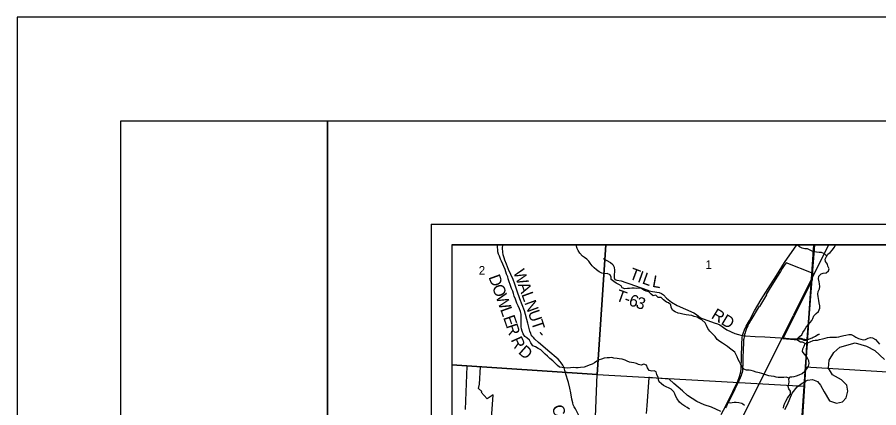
# Model space of a CAD drawing. Extents: x 39.8 to 73.8, y 13 to 35.
# Drawn here: x 39.763 to 43.927, y 33.079 to 34.965 of the extents above; entities that cross this region are included whole.
import ezdxf

# ---------------------------------------------------------------- set-up
doc = ezdxf.new("R2010")
doc.units = 0
for name, color, linetype in [('GM_X_Corporation', 7, 'Continuous'), ('GM_X_County_Road', 7, 'Continuous'), ('GM_X_County_Road_Text', 7, 'Continuous'), ('GM_X_Minor_River', 7, 'Continuous'), ('GM_X_Rail_Line', 7, 'Continuous'), ('GM_X_Section_Text', 7, 'Continuous'), ('GM_X_State_Route', 7, 'Continuous'), ('GM_X_Township_Road', 7, 'Continuous'), ('GM_X_Township_Road_Text', 7, 'Continuous'), ('SH_Border', 7, 'Continuous'), ('SH_Cut_Line', 7, 'Continuous'), ('SH_Data', 7, 'Continuous')]:
    doc.layers.add(name, color=color, linetype=linetype)

msp = doc.modelspace()

# ---------------------------------------------------------------- linework, layer by layer
at = {"layer": 'GM_X_Corporation'}
for points in [[(42.6077, 33.865), (41.863, 33.865), (41.863, 33.2861), (42.566, 33.2401)], [(43.6132, 33.865), (42.6077, 33.865), (42.566, 33.2401), (43.567, 33.1836), (43.573, 33.2772)], [(44.6253, 33.865), (43.6132, 33.865), (43.573, 33.2772), (44.5795, 33.2157)], [(41.863, 33.2861), (41.863, 32.2795), (42.505, 32.2334), (42.5452, 32.7074), (42.566, 33.2401)], [(43.573, 33.2772), (44.5795, 33.2157), (44.516, 32.1957), (43.5036, 32.2603), (43.567, 33.1836)], [(43.567, 33.1836), (43.5036, 32.2603), (43.4969, 32.1712), (42.505, 32.2334), (42.5452, 32.7074), (42.566, 33.2401)]]:
    msp.add_lwpolyline(points, close=True, dxfattribs=at)
for points in [[(43.3481, 29.9766), (43.3525, 30.036), (43.3561, 30.0855), (43.3611, 30.1536), (43.3611, 30.1764), (43.4119, 30.9413), (43.4278, 31.1804), (43.4594, 31.6102), (43.4604, 31.6234), (43.4879, 31.9992), (43.5004, 32.1696), (43.5417, 32.788), (43.542, 32.7932), (43.5449, 32.8368), (43.546, 32.8532), (43.5465, 32.861), (43.5681, 33.1854), (43.5817, 33.4098), (43.6158, 33.865), (41.863, 33.865), (41.863, 28.2309)], [(48.663, 33.865), (43.6158, 33.865), (43.5817, 33.4098), (43.5681, 33.1854), (43.5465, 32.861), (43.546, 32.8532), (43.5449, 32.8368), (43.542, 32.7932), (43.5417, 32.788), (43.5004, 32.1696), (43.4879, 31.9992), (43.4604, 31.6234), (43.4594, 31.6102), (43.4278, 31.1804), (43.4119, 30.9413), (43.3611, 30.1764), (43.3611, 30.1536), (43.3561, 30.0855), (43.3525, 30.036), (43.3481, 29.9766)], [(43.557, 33.0409), (43.5667, 33.1746), (43.5752, 33.2909), (43.5789, 33.3426), (43.5793, 33.3485), (43.5822, 33.3889), (43.5833, 33.4047), (43.5793, 33.4041), (43.5752, 33.4039), (43.5712, 33.404), (43.5671, 33.4044), (43.5632, 33.4053), (43.5593, 33.4064), (43.5498, 33.4096), (43.5472, 33.4103), (43.5445, 33.4106), (43.5418, 33.4104), (43.5391, 33.4099), (43.5337, 33.4084), (43.5298, 33.4075), (43.5259, 33.4069), (43.5218, 33.4067), (43.5178, 33.4069), (43.4639, 33.4121), (43.4658, 33.4158), (43.467, 33.4183), (43.6068, 33.6965), (43.6088, 33.7216), (43.6092, 33.7266), (43.4789, 33.7796), (43.4697, 33.7657), (43.4608, 33.7517), (43.452, 33.7375), (43.438, 33.7143), (43.4372, 33.7148), (43.4026, 33.6574), (43.3833, 33.6256), (43.3842, 33.6251), (43.3499, 33.5684), (43.3491, 33.5689), (43.309, 33.5025), (43.303, 33.4927), (43.298, 33.4839), (43.2934, 33.475), (43.2893, 33.4658), (43.2856, 33.4564), (43.2823, 33.4468), (43.2806, 33.4412), (43.2785, 33.433), (43.2778, 33.43), (43.2771, 33.4271), (43.2761, 33.4217), (43.2746, 33.4126), (43.2739, 33.4067), (43.2733, 33.4008), (43.273, 33.3962), (43.2727, 33.3903), (43.2727, 33.3899), (43.2727, 33.3894), (43.2726, 33.3885), (43.2718, 33.3614), (43.2704, 33.3175), (43.2697, 33.2938), (43.2696, 33.291), (43.2692, 33.2832), (43.2686, 33.2755), (43.2677, 33.2678), (43.2695, 33.2675), (43.2695, 33.2671), (43.2687, 33.2618), (43.2678, 33.2565), (43.2662, 33.2488), (43.2643, 33.2412), (43.2627, 33.2352), (43.2609, 33.2293), (43.2602, 33.2295), (43.2591, 33.2299), (43.2587, 33.2287), (43.2583, 33.2274), (43.2569, 33.2234), (43.254, 33.2158), (43.2509, 33.2083), (43.2475, 33.2009), (43.247, 33.1999), (43.2449, 33.1957), (43.2198, 33.1444), (43.2006, 33.1069), (43.1988, 33.1033), (43.1974, 33.1005), (43.1949, 33.0954), (43.1927, 33.0906), (43.1904, 33.0859), (43.1882, 33.0812), (43.186, 33.0765)], [(42.0545, 33.0285), (42.0613, 33.1171), (42.0632, 33.1409), (42.0336, 33.1218), (42.0049, 33.154), (42.0081, 33.1569), (41.9916, 33.1714), (41.9976, 33.1929), (42.0024, 33.2761), (41.9362, 33.2801), (41.9283, 33.0712)], [(43.1639, 33.0603), (43.119, 33.082), (43.0827, 33.0938), (43.0476, 33.1092), (43.0027, 33.1387), (42.9783, 33.16), (42.9364, 33.1965), (42.9144, 33.2176), (42.8338, 33.2233), (42.8184, 33.2243), (42.8154, 33.2245), (42.812, 33.178), (42.8053, 33.0892), (42.8024, 33.0506)]]:
    msp.add_lwpolyline(points, dxfattribs=at)
at = {"layer": 'GM_X_County_Road'}
for points in [[(42.4147, 33.2426), (42.4097, 33.2589), (42.4058, 33.2716), (42.3998, 33.2839), (42.3916, 33.296), (42.3865, 33.303), (42.3781, 33.3131), (42.3685, 33.3223), (42.3379, 33.3481), (42.2831, 33.3937), (42.2653, 33.4101), (42.2575, 33.4179), (42.2518, 33.4248), (42.2477, 33.4318), (42.2446, 33.4382), (42.2411, 33.4486), (42.2306, 33.4878), (42.2142, 33.5466), (42.1923, 33.6047), (42.18, 33.6428), (42.1685, 33.6765), (42.1599, 33.698), (42.1379, 33.747), (42.1275, 33.7724), (42.1201, 33.7919), (42.1162, 33.803), (42.1123, 33.8174), (42.1101, 33.8305), (42.109, 33.8502), (42.1097, 33.865)], [(42.5359, 32.9279), (42.5342, 32.9315), (42.5108, 32.9743), (42.4605, 33.0731), (42.4552, 33.0827), (42.4505, 33.0936), (42.4476, 33.1026), (42.4441, 33.1205), (42.4386, 33.1514), (42.4341, 33.1736), (42.4275, 33.2003), (42.4257, 33.206), (42.415, 33.2417), (42.4147, 33.2426)]]:
    msp.add_lwpolyline(points, dxfattribs=at)
at = {"layer": 'GM_X_Minor_River'}
for p, q in [((43.5792, 33.3903), (43.5951, 33.3975)), ((43.5951, 33.3975), (43.6094, 33.4039)), ((43.6094, 33.4039), (43.6197, 33.4047)), ((43.6197, 33.4047), (43.6303, 33.4058)), ((43.6303, 33.4058), (43.6412, 33.4081)), ((43.6412, 33.4081), (43.6545, 33.4119)), ((43.6545, 33.4119), (43.6677, 33.4153)), ((43.6677, 33.4153), (43.6787, 33.4179)), ((43.6787, 33.4179), (43.6897, 33.4191)), ((43.6897, 33.4191), (43.6995, 33.4198)), ((43.6995, 33.4198), (43.7098, 33.4195)), ((43.7098, 33.4195), (43.7219, 33.4199)), ((43.7219, 33.4199), (43.7344, 33.4221)), ((43.7344, 33.4221), (43.7446, 33.4248)), ((43.7446, 33.4248), (43.7579, 33.4286)), ((43.7579, 33.4286), (43.7685, 33.4301)), ((43.7685, 33.4301), (43.7821, 33.4327)), ((43.7821, 33.4327), (43.7942, 33.4331)), ((43.7942, 33.4331), (43.8067, 33.4271)), ((43.8067, 33.4271), (43.8169, 33.4206)), ((43.8169, 33.4206), (43.8283, 33.4134)), ((43.8283, 33.4134), (43.8408, 33.41)), ((43.8408, 33.41), (43.8529, 33.407)), ((43.8529, 33.407), (43.8627, 33.4081)), ((43.8627, 33.4081), (43.876, 33.4149)), ((43.876, 33.4149), (43.8866, 33.418)), ((43.8866, 33.418), (43.8964, 33.4172)), ((43.8964, 33.4172), (43.9108, 33.4085)), ((43.9108, 33.4085), (43.9218, 33.396)), ((43.9218, 33.396), (43.9301, 33.3854)), ((43.5708, 33.3891), (43.5792, 33.3903))]:
    msp.add_line(p, q, dxfattribs=at)
for points in [[(42.2261, 33.4162), (42.2162, 33.4238), (42.2083, 33.4355), (42.2034, 33.4488), (42.2007, 33.4602), (42.1988, 33.47), (42.1985, 33.4844), (42.1985, 33.4958), (42.1992, 33.5057), (42.1992, 33.5185), (42.1985, 33.531), (42.1951, 33.5432), (42.1901, 33.5561), (42.1845, 33.5705), (42.1784, 33.5837), (42.1743, 33.5932), (42.1705, 33.6034), (42.1652, 33.6182), (42.1618, 33.6311), (42.1576, 33.6417), (42.1516, 33.6542), (42.1489, 33.6641), (42.1459, 33.6739), (42.141, 33.6876), (42.1364, 33.7012), (42.1334, 33.7118), (42.1285, 33.7243), (42.1247, 33.7361), (42.1209, 33.7471), (42.1152, 33.7607), (42.1099, 33.7732), (42.1031, 33.7872), (42.099, 33.7971), (42.0937, 33.8107), (42.0891, 33.821), (42.0853, 33.8316), (42.0853, 33.8414), (42.0842, 33.8543), (42.0839, 33.865)], [(43.4945, 33.222), (43.4799, 33.2261), (43.4689, 33.225), (43.4553, 33.225), (43.4413, 33.2258), (43.4311, 33.2269), (43.4209, 33.2296), (43.4069, 33.2314), (43.3963, 33.2333), (43.3611, 33.2451), (43.3501, 33.2477), (43.3342, 33.2511), (43.3213, 33.2564), (43.3107, 33.2587), (43.3001, 33.2599), (43.2876, 33.261), (43.2747, 33.2659), (43.266, 33.2777), (43.2588, 33.2905), (43.2539, 33.3004), (43.2482, 33.3121), (43.2422, 33.3243), (43.2365, 33.3375), (43.2308, 33.347), (43.2191, 33.3576), (43.2062, 33.3667), (43.1956, 33.3751), (43.182, 33.3838), (43.1722, 33.3913), (43.1585, 33.3997), (43.1464, 33.4088), (43.1362, 33.4224), (43.1241, 33.4361), (43.1105, 33.4489), (43.101, 33.4622), (43.095, 33.4755), (43.0874, 33.4895), (43.0726, 33.5039), (43.0624, 33.5081), (43.0488, 33.516), (43.0355, 33.5202), (43.0238, 33.5244), (43.0087, 33.5262), (42.9962, 33.5278), (42.9803, 33.5308), (42.9678, 33.5334), (42.9575, 33.5365), (42.9432, 33.5422), (42.9307, 33.5505), (42.9242, 33.5641), (42.9227, 33.5766), (42.9114, 33.5854), (42.9004, 33.5888), (42.8871, 33.6001), (42.8747, 33.6107), (42.861, 33.6115), (42.85, 33.6232), (42.8364, 33.6195), (42.8266, 33.6282), (42.816, 33.6392), (42.8035, 33.6422), (42.7921, 33.6467), (42.7796, 33.6543), (42.7668, 33.6562), (42.7558, 33.6543), (42.7444, 33.6558), (42.7338, 33.657), (42.7225, 33.6554), (42.7126, 33.6543), (42.6998, 33.6539), (42.6873, 33.6577), (42.6816, 33.6672), (42.6714, 33.674), (42.657, 33.6808), (42.646, 33.6884), (42.6343, 33.699), (42.6331, 33.7096), (42.6282, 33.7217), (42.615, 33.7267), (42.6006, 33.7263), (42.5877, 33.7289), (42.5756, 33.735), (42.5631, 33.7445), (42.5518, 33.7543), (42.5423, 33.7649), (42.5325, 33.7767), (42.526, 33.7865), (42.5158, 33.7972), (42.5052, 33.8044), (42.4954, 33.8112), (42.4817, 33.826), (42.4742, 33.8385), (42.47, 33.8483), (42.4639, 33.8638), (42.4633, 33.865)], [(43.6755, 33.8118), (43.6644, 33.822), (43.6508, 33.8288), (43.6391, 33.8295), (43.6266, 33.8299), (43.6122, 33.8322), (43.5989, 33.839), (43.5831, 33.8458), (43.5698, 33.8458), (43.5566, 33.8496), (43.5433, 33.8564), (43.5328, 33.865)], [(43.6341, 33.6169), (43.633, 33.6279), (43.6341, 33.6408), (43.6402, 33.6537), (43.6421, 33.6643), (43.6406, 33.6776), (43.6383, 33.6874), (43.6364, 33.7011), (43.6372, 33.7147), (43.6481, 33.7253), (43.6587, 33.7291), (43.6724, 33.731), (43.6845, 33.7409), (43.6871, 33.7503), (43.6807, 33.7632), (43.6788, 33.7731), (43.669, 33.786), (43.6675, 33.7958), (43.6739, 33.8095), (43.6811, 33.8201), (43.6925, 33.8295), (43.7038, 33.8413), (43.711, 33.8523), (43.7182, 33.8637), (43.7194, 33.865)], [(43.4663, 33.0764), (43.4674, 33.0878), (43.4723, 33.1015), (43.4772, 33.1113), (43.486, 33.125), (43.4924, 33.1348), (43.5, 33.145), (43.5007, 33.1587), (43.4928, 33.1701), (43.4894, 33.1818), (43.492, 33.1947), (43.4932, 33.2049), (43.4924, 33.2171), (43.497, 33.2277), (43.5068, 33.2288), (43.5182, 33.2299), (43.5291, 33.233), (43.5424, 33.2379), (43.556, 33.2444), (43.5697, 33.2553), (43.5799, 33.2675), (43.5878, 33.28), (43.5909, 33.2929), (43.5894, 33.305), (43.5848, 33.3145), (43.5776, 33.3262), (43.5659, 33.3399), (43.5591, 33.3505), (43.5602, 33.3641), (43.5663, 33.3762), (43.5708, 33.3891), (43.5583, 33.3956), (43.5485, 33.3959), (43.5364, 33.4035), (43.5341, 33.4138), (43.5443, 33.4229), (43.5557, 33.4316), (43.5599, 33.4422), (43.5678, 33.4536), (43.5765, 33.4676), (43.5879, 33.4809), (43.5962, 33.4903), (43.6042, 33.4998), (43.6087, 33.51), (43.6136, 33.5233), (43.625, 33.5335), (43.636, 33.5445), (43.6428, 33.5597), (43.6424, 33.5718), (43.639, 33.5858), (43.6371, 33.5965), (43.6349, 33.6067), (43.6341, 33.6169)], [(43.0127, 33.0722), (43.0002, 33.0802), (42.9904, 33.087), (42.9756, 33.0957), (42.9635, 33.1056), (42.9525, 33.1218), (42.9468, 33.134), (42.9416, 33.1461), (42.9359, 33.156), (42.9241, 33.1692), (42.9135, 33.1741), (42.8995, 33.1806), (42.887, 33.1859), (42.8761, 33.1938), (42.8658, 33.2048), (42.8621, 33.2143), (42.8606, 33.2245), (42.8541, 33.2397), (42.8507, 33.2526), (42.8409, 33.2568), (42.8307, 33.256), (42.8166, 33.2594), (42.8095, 33.2719), (42.8045, 33.2852), (42.792, 33.2893), (42.7792, 33.2848), (42.7655, 33.2886), (42.7553, 33.2927), (42.7436, 33.2958), (42.7318, 33.2977), (42.722, 33.2992), (42.711, 33.3041), (42.7008, 33.309), (42.686, 33.3136), (42.6717, 33.3151), (42.6618, 33.317), (42.6471, 33.3185), (42.6368, 33.3212), (42.6255, 33.3208), (42.6137, 33.3208), (42.5997, 33.3185), (42.5865, 33.3143), (42.5751, 33.3101), (42.5649, 33.3037), (42.5528, 33.2957), (42.5422, 33.2897), (42.5278, 33.284), (42.516, 33.2802), (42.5024, 33.2753), (42.4861, 33.2726), (42.4733, 33.2722), (42.4627, 33.2715), (42.4494, 33.273), (42.4365, 33.2722), (42.4222, 33.2707), (42.4097, 33.2718), (42.3964, 33.273), (42.3835, 33.2745), (42.3737, 33.2828), (42.3616, 33.2961), (42.3514, 33.3056), (42.3374, 33.3162), (42.3264, 33.3275), (42.3154, 33.3385), (42.3052, 33.3476), (42.2935, 33.3582), (42.281, 33.3647), (42.2673, 33.3734), (42.2556, 33.3787), (42.2454, 33.392), (42.2382, 33.406), (42.2261, 33.4162)]]:
    msp.add_lwpolyline(points, dxfattribs=at)
at = {"layer": 'GM_X_Rail_Line'}
msp.add_line((43.6843, 33.865), (43.5136, 33.5221), dxfattribs=at)
for points in [[(42.9175, 32.205), (42.9584, 32.355), (43.0035, 32.4874), (43.0092, 32.5034), (43.0152, 32.5194), (43.0216, 32.5352), (43.0284, 32.5508), (43.0355, 32.5663), (43.0429, 32.5817), (43.1926, 32.8811), (43.5132, 33.5223)], [(43.4731, 33.0698), (43.4858, 33.0949), (43.509, 33.1487), (43.5333, 33.1797), (43.5566, 33.1972), (43.5833, 33.2117), (43.607, 33.2162), (43.6309, 33.2065), (43.6459, 33.1873), (43.6629, 33.1558), (43.6892, 33.1119), (43.7223, 33.1009), (43.7512, 33.1081), (43.7688, 33.1274), (43.7778, 33.1596), (43.7722, 33.1885), (43.7471, 33.2136), (43.7041, 33.2387), (43.6848, 33.2696), (43.6878, 33.3083), (43.7095, 33.345), (43.7395, 33.3718), (43.8123, 33.3919), (43.8675, 33.3768), (43.9081, 33.3558), (43.9544, 33.3126)]]:
    msp.add_lwpolyline(points, dxfattribs=at)
at = {"layer": 'GM_X_State_Route'}
for points in [[(43.4711, 33.78), (43.4742, 33.7851), (43.5057, 33.8292), (43.5316, 33.865)], [(43.166, 33.0461), (43.1766, 33.0667), (43.1952, 33.1049), (43.2452, 33.2075), (43.2538, 33.2303), (43.2596, 33.252), (43.2622, 33.2671), (43.2655, 33.3849), (43.2673, 33.4176), (43.2688, 33.428), (43.2714, 33.438), (43.2776, 33.4547), (43.286, 33.4727), (43.3028, 33.5003), (43.3265, 33.5464), (43.3591, 33.6015), (43.3918, 33.6555), (43.432, 33.7178), (43.4711, 33.78)]]:
    msp.add_lwpolyline(points, dxfattribs=at)
at = {"layer": 'GM_X_Township_Road'}
msp.add_line((42.5954, 33.8004), (42.6129, 33.7907), dxfattribs=at)
for points in [[(42.6129, 33.7907), (42.6278, 33.7824), (42.63, 33.7806)], [(42.63, 33.7806), (42.6423, 33.7711), (42.6484, 33.7578), (42.6504, 33.7415), (42.6475, 33.7157), (42.6483, 33.7066), (42.6518, 33.6983), (42.6617, 33.6945), (42.6822, 33.6912), (42.705, 33.6842), (42.7184, 33.6793), (42.8103, 33.6465)], [(42.8103, 33.6465), (42.8177, 33.6439), (42.8337, 33.6398), (42.8648, 33.6351), (42.8762, 33.6302), (42.8862, 33.6238), (42.9011, 33.608), (42.9255, 33.5887), (42.9518, 33.5734), (43.0329, 33.5378), (43.0466, 33.5288), (43.0653, 33.5126), (43.1313, 33.4896), (43.1483, 33.4849), (43.1595, 33.4795), (43.1765, 33.4662), (43.1926, 33.4545), (43.231, 33.4382), (43.2498, 33.432), (43.2605, 33.4296), (43.2688, 33.428)], [(43.2688, 33.428), (43.2751, 33.4269), (43.2834, 33.426), (43.3296, 33.4237), (43.3758, 33.4212), (43.4528, 33.4162), (43.47, 33.4149), (43.4719, 33.4147)], [(43.4719, 33.4147), (43.4785, 33.4144), (43.5098, 33.412), (43.5191, 33.4118), (43.5222, 33.4119), (43.5283, 33.4126), (43.5344, 33.4139), (43.5404, 33.4153), (43.5435, 33.4156), (43.5466, 33.4154), (43.5496, 33.4149), (43.5555, 33.413), (43.5614, 33.4109), (43.5644, 33.4101), (43.5674, 33.4094), (43.5724, 33.4088), (43.578, 33.4087), (43.5796, 33.4088), (43.5819, 33.4092)], [(43.5819, 33.4092), (43.5848, 33.41), (43.5885, 33.411), (43.5926, 33.4122), (43.5965, 33.4135), (43.6008, 33.4151), (43.6054, 33.417), (43.6103, 33.4191), (43.6113, 33.4196), (43.6142, 33.421), (43.6184, 33.4233), (43.6214, 33.4252), (43.6331, 33.4322), (43.6351, 33.4334), (43.6371, 33.4341), (43.6394, 33.4346), (43.6412, 33.4347)], [(43.1952, 33.1049), (43.2084, 33.1035), (43.2181, 33.1045), (43.2278, 33.1058), (43.2385, 33.1067), (43.2504, 33.105), (43.2644, 33.1015), (43.2702, 33.0979), (43.2783, 33.0912)]]:
    msp.add_lwpolyline(points, dxfattribs=at)
at = {"layer": 'SH_Border'}
for points in [[(40.263, 34.465), (41.263, 34.465), (41.263, 13.465), (40.263, 13.465)], [(41.263, 34.465), (73.263, 34.465), (73.263, 13.465), (41.263, 13.465)]]:
    msp.add_lwpolyline(points, close=True, dxfattribs=at)
at = {"layer": 'SH_Cut_Line'}
msp.add_lwpolyline([(39.763, 12.965), (73.763, 12.965), (73.763, 34.965), (39.763, 34.965)], close=True, dxfattribs=at)
at = {"layer": 'SH_Data'}
for p, q in [((41.763, 33.965), (48.763, 33.965)), ((41.763, 33.965), (41.763, 26.965)), ((41.863, 33.865), (41.863, 27.065)), ((41.863, 33.865), (48.663, 33.865))]:
    msp.add_line(p, q, dxfattribs=at)

# ---------------------------------------------------------------- texts
at = {"layer": 'GM_X_County_Road_Text'}
for s, rotation, p in [('W', 290.003, (42.1592, 33.7355)), ('D', 289.8935, (42.04, 33.7104)), ('O', 289.8961, (42.057, 33.6634)), ('A', 290.0018, (42.1818, 33.6736)), ('W', 289.8796, (42.074, 33.6163)), ('L', 289.9978, (42.1989, 33.6266)), ('L', 289.7605, (42.0964, 33.5545)), ('N', 289.9327, (42.2134, 33.5867)), ('E', 289.4324, (42.1107, 33.5146)), ('U', 288.7356, (42.2303, 33.54)), ('R', 287.8993, (42.1247, 33.4749)), ('T', 288.1571, (42.2463, 33.4928)), ('-', 309.5649, (42.2707, 33.4322)), ('R', 294.1319, (42.1472, 33.4076)), ('D', 318.2793, (42.1816, 33.3441)), ('C', 289.1101, (42.3449, 33.0825))]:
    msp.add_text(s, height=0.0568, rotation=rotation, dxfattribs=at).set_placement(p)
at = {"layer": 'GM_X_Section_Text'}
for s, p in [('1', (43.089, 33.7487)), ('2', (41.9936, 33.7215))]:
    msp.add_text(s, height=0.0419, rotation=0, dxfattribs=at).set_placement(p)
at = {"layer": 'GM_X_Township_Road_Text'}
for s, height, rotation, p in [('T', 0.0568, 339.468, (42.717, 33.7034)), ('I', 0.0568, 340.1055, (42.7575, 33.6883)), ('L', 0.0568, 340.3468, (42.7797, 33.6803)), ('L', 0.0568, 349.6593, (42.8292, 33.6634)), ('T', 0.0568, 340.2706, (42.6522, 33.5981)), ('-', 0.0568, 340.3421, (42.6923, 33.5838)), ('6', 0.0568, 340.6221, (42.7145, 33.5758)), ('3', 0.0568, 341.7988, (42.7487, 33.5638)), ('RD', 0.05682, 328.8789, (43.1135, 33.5139))]:
    msp.add_text(s, height=height, rotation=rotation, dxfattribs=at).set_placement(p)

doc.saveas('drawing.dxf')
